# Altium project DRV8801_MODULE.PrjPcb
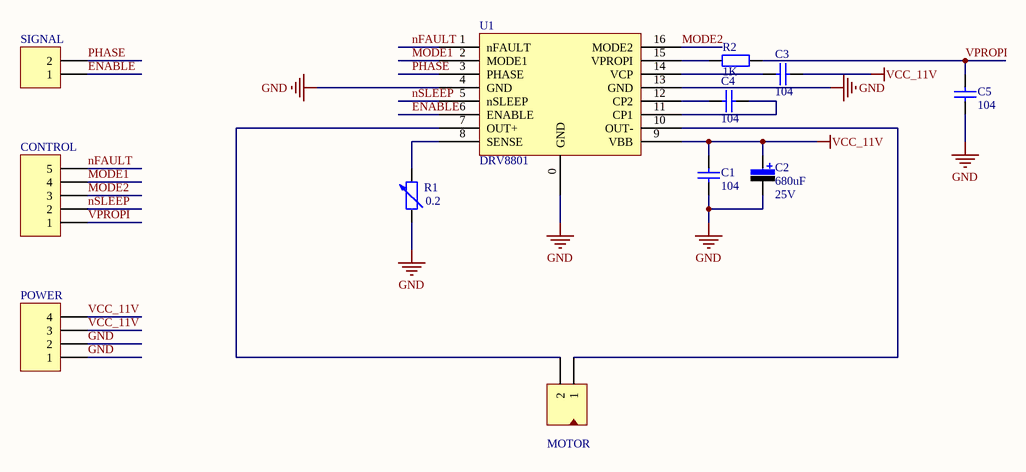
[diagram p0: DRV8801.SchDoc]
1 sheet, 12 parts. Net scope: global (net labels, ports and power ports of the same name join across sheets).
Board file: DRV8801.PcbDoc

## Sheet DRV8801.SchDoc
size A

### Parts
C1  value 104  [C-0603]  (hidden comment: Cap-S)
C2  value 680uF  Vol: 25V  [C-RB-5.0/10]  (hidden comment: Cap-Pol-ER)
C3  value 104  [C-0603]  (hidden comment: Cap-S)
C4  value 104  [C-0603]  (hidden comment: Cap-S)
C5  value 104  [C-0603]  (hidden comment: Cap-S)
CONTROL  Header 5  [HDR1X5]  (value not drawn)
MOTOR  Header 2  [HDR2X1-2.54]  (value not drawn)
POWER  Header 4  [HDR1X4]  (value not drawn)
R1  value 0.2  [AXIAL-0.6]  (hidden comment: Res Adj2)
R2  value 1K  [0603-1]  (hidden comment: Res1)
SIGNAL  Header 2  [HDR1X2]  (value not drawn)
U1  DRV8801  [HTSSOP16]

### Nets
GND: C1.1 C2.2 C5.1 POWER.1 POWER.2 R1.1 U1.0(GND) U1.4(GND) U1.13(GND)
VCC_11V: C1.2 C2.1 C3.1 POWER.3 POWER.4 U1.9(VBB)
ENABLE: SIGNAL.1 U1.6(ENABLE)
MODE1: CONTROL.4 U1.2(MODE1)
MODE2: CONTROL.3 U1.16(MODE2)
nFAULT: CONTROL.5 U1.1(nFAULT)
nSLEEP: CONTROL.2 U1.5(nSLEEP)
PHASE: SIGNAL.2 U1.3(PHASE)
VPROPI: C5.2 CONTROL.1 R2.2
NetC3_2: C3.2 U1.14(VCP)
NetC4_1: C4.1 U1.11(CP1)
NetC4_2: C4.2 U1.12(CP2)
NetMOTOR_1: MOTOR.1 U1.10(OUT-)
NetMOTOR_2: MOTOR.2 U1.7(OUT+)
NetR1_2: R1.2 U1.8(SENSE)
NetR2_1: R2.1 U1.15(VPROPI)

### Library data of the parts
C1 C3-C5 = Cap-S: 贴片瓷片电容
C2 = Cap-Pol-ER: 插件电解电容
CONTROL = Header 5: Header, 5-Pin
MOTOR = Header 2: 接插件
POWER = Header 4: Header, 4-Pin
R1 = Res Adj2: Variable Resistor; Set Position: 0.5
R2 = Res1: 贴片电阻
SIGNAL = Header 2: Header, 2-Pin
